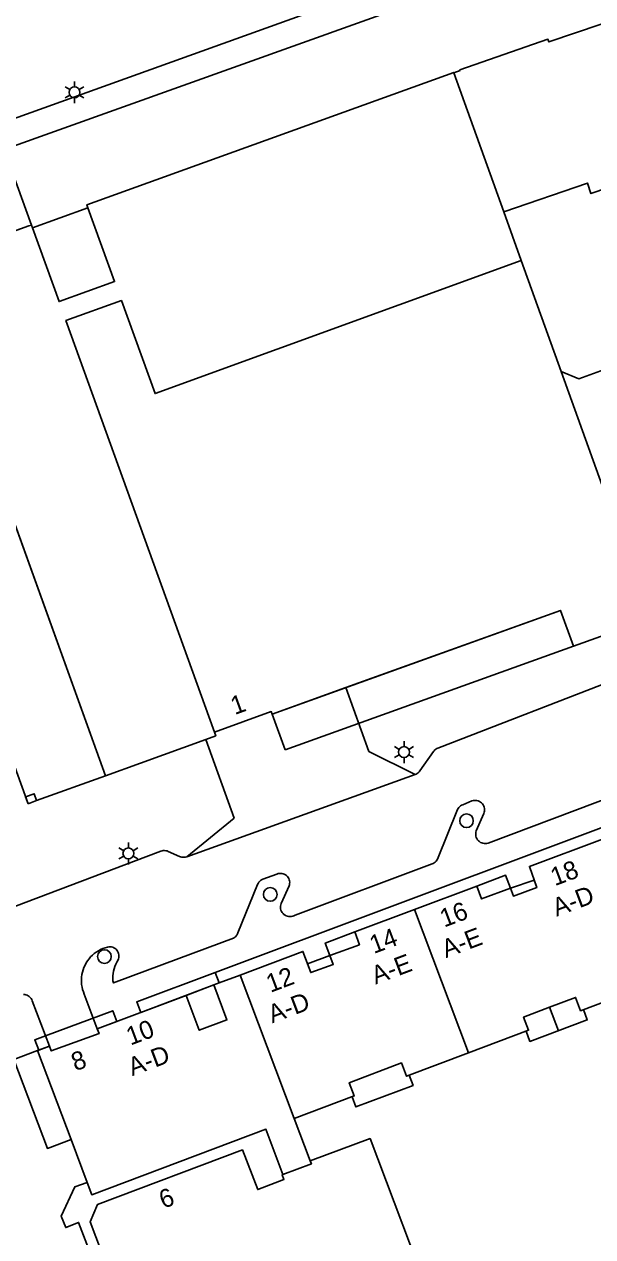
# Model space of a CAD drawing. Extents: x 122462 to 123306, y 485548 to 486417.
# Drawn here: x 122519.5 to 122566.2, y 485673.5 to 485773.2 of the extents above; entities that cross this region are included whole.
import ezdxf

# ---------------------------------------------------------------- set-up
doc = ezdxf.new("R2010")
doc.units = 0
for name, color, linetype in [('B-WE-IE-MEUBILAIR_WEGMEUBILAIR_VERKEERSBORD-S', 7, 'Continuous'), ('Level 1', 7, 'Continuous'), ('Level 10', 7, 'Continuous'), ('Level 11', 7, 'Continuous'), ('Level 17', 7, 'Continuous'), ('Level 19', 7, 'Continuous'), ('Level 22', 7, 'Continuous'), ('Level 34', 7, 'Continuous'), ('Level 4', 7, 'Continuous'), ('Level 50', 7, 'Continuous'), ('Level 53', 7, 'Continuous'), ('N-WE-AL-T25', 7, 'Continuous')]:
    doc.layers.add(name, color=color, linetype=linetype)

msp = doc.modelspace()

# ---------------------------------------------------------------- linework, layer by layer
at = {"layer": 'Level 1'}
for p, q in [((122524.761, 485758.082), (122520.199, 485756.429)), ((122560.372, 485753.746), (122558.935, 485757.75)), ((122563.647, 485744.62), (122560.372, 485753.746)), ((122570.939, 485724.289), (122563.647, 485744.62)), ((122532.832, 485693.313), (122535.1, 485694.168)), ((122525.531, 485690.561), (122532.832, 485693.313)), ((122518.673, 485688.045), (122520.616, 485688.777)), ((122520.616, 485688.777), (122521.591, 485689.151)), ((122541.714, 485683.189), (122543.026, 485679.702))]:
    msp.add_line(p, q, dxfattribs=at)
for points in [[(122595.705, 485783.261), (122588.35, 485780.749), (122588.42, 485780.539), (122577.601, 485776.821), (122577.531, 485777.031), (122573.371, 485775.601), (122573.443, 485775.393), (122562.65, 485771.719), (122562.57, 485771.939), (122555.33, 485769.42), (122555.347, 485769.372), (122554.835, 485769.176)], [(122558.935, 485757.75), (122565.807, 485760.105), (122566.103, 485759.241), (122573.182, 485761.667), (122572.886, 485762.531), (122575.552, 485763.445), (122576.058, 485761.968), (122583.208, 485764.419), (122582.702, 485765.895), (122585.619, 485766.895), (122585.915, 485766.032), (122592.763, 485768.378), (122592.467, 485769.242), (122599.667, 485771.71)], [(122554.835, 485769.176), (122554.82, 485769.209), (122524.67, 485758.329), (122524.761, 485758.082)], [(122520.199, 485756.429), (122520.11, 485756.65), (122519.901, 485756.601), (122516.856, 485755.503), (122511.049, 485753.41), (122518.197, 485733.594), (122526.209, 485711.38), (122529.079, 485712.419), (122534.438, 485714.36)], [(122545.965, 485718.624), (122563.597, 485724.974), (122564.658, 485722.028), (122570.939, 485724.289)], [(122535.163, 485714.962), (122539.822, 485716.649), (122539.898, 485716.439), (122545.965, 485718.624)], [(122534.438, 485714.36), (122535.269, 485714.66), (122535.163, 485714.962)], [(122551.589, 485700.372), (122556.719, 485702.299), (122557.108, 485701.246), (122559.488, 485702.127), (122559.73, 485701.474), (122561.644, 485702.183), (122561.039, 485703.92), (122567.04, 485706.164)], [(122537.268, 485694.984), (122542.429, 485696.929), (122543.077, 485695.183), (122544.916, 485695.863), (122544.651, 485696.58), (122547.068, 485697.473), (122546.689, 485698.529), (122551.589, 485700.372)], [(122535.1, 485694.168), (122535.555, 485694.339), (122537.268, 485694.984)], [(122571.262, 485694.96), (122570.331, 485694.609), (122570.543, 485694.046), (122565.253, 485692.054), (122564.842, 485693.145), (122562.701, 485692.339)], [(122562.701, 485692.339), (122560.561, 485691.533), (122560.972, 485690.442), (122556.033, 485688.582)], [(122521.591, 485689.151), (122521.739, 485688.743), (122525.672, 485690.172), (122525.531, 485690.561)], [(122556.033, 485688.582), (122550.942, 485686.664), (122550.531, 485687.755), (122546.233, 485686.137), (122546.644, 485685.045), (122541.714, 485683.189)], [(122543.026, 485679.702), (122547.951, 485681.541), (122553.241, 485667.511), (122546.311, 485664.908), (122547.777, 485661.013)]]:
    msp.add_lwpolyline(points, dxfattribs=at)
at = {"layer": 'Level 10'}
for points in [[(122519.84, 485709.069), (122520.535, 485709.334), (122526.209, 485711.38), (122511.049, 485753.41), (122519.901, 485756.601), (122520.11, 485756.65), (122514.9, 485771.059), (122514.741, 485770.971), (122514.241, 485770.791), (122514.141, 485771.021), (122508.443, 485768.964), (122508.528, 485768.729), (122507.89, 485768.498), (122507.805, 485768.733), (122506.416, 485768.232), (122506.501, 485767.997), (122505.862, 485767.766), (122505.777, 485768.001), (122500.08, 485765.961), (122500.159, 485765.742), (122499.489, 485765.499), (122519.84, 485709.069)], [(122540.959, 485713.492), (122539.898, 485716.439), (122563.597, 485724.974), (122564.658, 485722.028), (122540.959, 485713.492)], [(122559.488, 485702.127), (122561.43, 485702.801), (122561.644, 485702.183), (122559.73, 485701.474), (122559.488, 485702.127)], [(122544.651, 485696.58), (122544.916, 485695.863), (122543.077, 485695.183), (122542.812, 485695.9), (122544.651, 485696.58)], [(122529.103, 485691.907), (122528.772, 485692.784), (122535.229, 485695.204), (122535.555, 485694.339), (122529.103, 485691.907)], [(122521.739, 485688.743), (122521.591, 485689.151), (122520.717, 485688.815), (122520.395, 485689.646), (122521.279, 485689.977), (122526.796, 485692.045), (122527.128, 485691.163), (122525.531, 485690.561), (122525.672, 485690.172), (122521.739, 485688.743)]]:
    msp.add_lwpolyline(points, dxfattribs=at)
at = {"layer": 'Level 11'}
for points in [[(122556.719, 485702.299), (122559.09, 485703.189), (122559.488, 485702.127)], [(122546.689, 485698.529), (122544.261, 485697.618), (122544.651, 485696.58)], [(122565.484, 485692.141), (122565.801, 485691.301), (122561.085, 485689.525), (122560.768, 485690.365)], [(122551.172, 485686.751), (122551.489, 485685.911), (122546.783, 485684.139), (122546.467, 485684.978)]]:
    msp.add_lwpolyline(points, dxfattribs=at)
at = {"layer": 'Level 17'}
msp.add_line((122551.651, 485711.476), (122532.876, 485704.714), dxfattribs=at)
for points in [[(122553.788, 485778.048), (122513.731, 485763.641)], [(122556.723, 485776.778), (122517.869, 485762.854)], [(122551.651, 485711.476), (122547.856, 485713.372), (122545.965, 485718.624)], [(122568.671, 485719.499), (122553.517, 485713.644), (122553.431, 485713.605), (122553.351, 485713.556), (122553.277, 485713.498), (122553.21, 485713.432), (122553.152, 485713.358), (122552.034, 485711.768), (122551.973, 485711.692), (122551.903, 485711.624), (122551.825, 485711.564), (122551.741, 485711.515), (122551.651, 485711.476)], [(122534.438, 485714.36), (122536.767, 485707.89), (122532.876, 485704.714)], [(122541.486, 485699.803), (122541.593, 485699.827), (122541.694, 485699.866), (122541.79, 485699.919), (122553.053, 485704.118), (122553.144, 485704.162), (122553.228, 485704.216), (122553.306, 485704.28), (122553.375, 485704.354), (122553.434, 485704.435), (122553.483, 485704.523), (122555.143, 485708.605), (122555.187, 485708.694), (122555.244, 485708.775), (122555.312, 485708.847), (122555.39, 485708.908), (122555.476, 485708.957), (122555.568, 485708.993), (122556.321, 485709.299), (122556.422, 485709.328), (122556.526, 485709.342), (122556.632, 485709.343), (122556.736, 485709.329), (122556.837, 485709.3), (122556.934, 485709.259), (122557.024, 485709.204), (122557.106, 485709.138), (122557.178, 485709.061), (122557.238, 485708.975), (122557.287, 485708.881), (122557.322, 485708.782), (122557.343, 485708.679), (122557.35, 485708.574), (122557.343, 485708.469), (122557.321, 485708.366), (122557.286, 485708.267), (122556.68, 485706.842), (122556.649, 485706.737), (122556.633, 485706.629), (122556.633, 485706.52), (122556.648, 485706.412), (122556.678, 485706.307), (122556.722, 485706.207), (122556.78, 485706.114), (122556.85, 485706.031), (122556.932, 485705.958), (122557.022, 485705.897), (122557.121, 485705.85), (122557.225, 485705.817), (122557.333, 485705.799), (122557.442, 485705.796), (122557.55, 485705.808), (122557.656, 485705.836), (122568.344, 485709.854)], [(122532.876, 485704.714), (122532.777, 485704.685), (122532.676, 485704.669), (122532.573, 485704.666), (122532.47, 485704.677), (122532.37, 485704.701), (122532.274, 485704.737), (122531.363, 485705.15), (122531.265, 485705.187), (122531.164, 485705.211), (122531.06, 485705.221), (122530.956, 485705.218), (122530.853, 485705.201), (122530.753, 485705.171), (122530.52, 485705.083), (122508.8, 485696.87)], [(122525.531, 485690.561), (122524.456, 485693.415), (122524.382, 485693.606), (122524.321, 485693.802), (122524.275, 485694.002), (122524.244, 485694.204), (122524.227, 485694.409), (122524.225, 485694.614), (122524.238, 485694.818), (122524.266, 485695.021), (122524.308, 485695.222), (122524.364, 485695.419), (122524.435, 485695.612), (122524.519, 485695.798), (122524.617, 485695.979), (122524.727, 485696.151), (122524.85, 485696.316), (122524.984, 485696.471), (122525.129, 485696.616), (122525.284, 485696.75), (122525.449, 485696.872), (122525.621, 485696.983), (122525.802, 485697.08), (122525.988, 485697.165), (122526.181, 485697.235), (122526.378, 485697.292), (122526.483, 485697.31), (122526.589, 485697.313), (122526.695, 485697.302), (122526.798, 485697.275), (122526.896, 485697.234), (122526.988, 485697.179), (122527.07, 485697.112), (122527.143, 485697.034), (122527.203, 485696.947), (122527.251, 485696.852), (122527.285, 485696.751), (122527.304, 485696.646), (122527.308, 485696.54), (122527.297, 485696.434), (122527.271, 485696.331), (122527.231, 485696.232), (122527.134, 485696.057), (122527.049, 485695.877), (122526.976, 485695.691), (122526.915, 485695.501), (122526.866, 485695.307), (122526.83, 485695.11), (122526.807, 485694.912), (122526.797, 485694.713), (122526.799, 485694.513), (122526.865, 485694.338), (122532.236, 485696.349), (122536.722, 485698.029), (122536.806, 485698.075), (122536.883, 485698.133), (122536.95, 485698.201), (122537.008, 485698.278), (122537.054, 485698.362), (122537.087, 485698.452), (122538.706, 485702.432), (122538.749, 485702.524), (122538.805, 485702.61), (122538.872, 485702.688), (122538.948, 485702.755), (122539.033, 485702.812), (122539.125, 485702.857), (122540.289, 485703.289), (122540.388, 485703.323), (122540.49, 485703.343), (122540.595, 485703.349), (122540.699, 485703.34), (122540.801, 485703.317), (122540.899, 485703.28), (122540.991, 485703.23), (122541.075, 485703.168), (122541.15, 485703.095), (122541.214, 485703.012), (122541.265, 485702.922), (122541.304, 485702.825), (122541.329, 485702.723), (122541.34, 485702.619), (122541.337, 485702.515), (122541.319, 485702.412), (122541.287, 485702.312), (122540.639, 485700.859), (122540.606, 485700.755), (122540.589, 485700.647), (122540.586, 485700.538), (122540.599, 485700.43), (122540.627, 485700.324), (122540.669, 485700.224), (122540.724, 485700.13), (122540.793, 485700.045), (122540.872, 485699.97), (122540.961, 485699.907), (122541.058, 485699.857), (122541.161, 485699.821), (122541.268, 485699.8), (122541.377, 485699.794), (122541.486, 485699.803)], [(122521.591, 485689.151), (122520.182, 485692.879), (122520.139, 485692.974), (122520.084, 485693.063), (122520.017, 485693.144), (122519.941, 485693.215), (122519.856, 485693.276), (122519.764, 485693.326), (122519.667, 485693.363), (122519.565, 485693.387), (122519.461, 485693.398)]]:
    msp.add_lwpolyline(points, dxfattribs=at)
at = {"layer": 'Level 19'}
msp.add_lwpolyline([(122568.113, 485745.115), (122565.115, 485743.997), (122563.647, 485744.62)], dxfattribs=at)
at = {"layer": 'Level 22'}
msp.add_line((122562.701, 485692.339), (122563.43, 485690.408), dxfattribs=at)
msp.add_lwpolyline([(122535.229, 485695.204), (122577.981, 485711.222), (122578.295, 485710.39)], dxfattribs=at)
at = {"layer": 'Level 34'}
msp.add_lwpolyline([(122519.84, 485709.069), (122519.633, 485709.646), (122520.332, 485709.898), (122520.535, 485709.334), (122519.84, 485709.069)], dxfattribs=at)
at = {"layer": 'Level 4'}
for p, q in [((122558.935, 485757.75), (122554.835, 485769.176)), ((122556.033, 485688.582), (122551.589, 485700.372)), ((122520.616, 485688.777), (122523.372, 485681.458)), ((122523.372, 485681.458), (122524.704, 485677.919))]:
    msp.add_line(p, q, dxfattribs=at)
for points in [[(122543.026, 485679.702), (122543.121, 485679.451), (122540.79, 485678.573), (122539.383, 485682.311), (122525.079, 485676.924), (122524.704, 485677.919)], [(122524.809, 485672.502), (122523.991, 485674.651), (122522.931, 485674.221), (122522.571, 485675.171), (122523.671, 485677.571), (122524.704, 485677.919)]]:
    msp.add_lwpolyline(points, dxfattribs=at)
at = {"layer": 'Level 50'}
for p, q in [((122523.656, 485768.018), (122523.656, 485768.468)), ((122523.266, 485767.793), (122522.876, 485768.018)), ((122524.435, 485768.018), (122524.045, 485767.793)), ((122523.266, 485767.343), (122522.876, 485767.118)), ((122523.656, 485766.668), (122523.656, 485767.118)), ((122524.435, 485767.118), (122524.045, 485767.343)), ((122550.349, 485713.541), (122549.959, 485713.766)), ((122550.739, 485713.766), (122550.739, 485714.216)), ((122551.518, 485713.766), (122551.128, 485713.541)), ((122550.349, 485713.091), (122549.959, 485712.866)), ((122550.739, 485712.416), (122550.739, 485712.866)), ((122551.518, 485712.866), (122551.128, 485713.091)), ((122528.088, 485705.436), (122528.088, 485705.886)), ((122527.698, 485705.211), (122527.308, 485705.436)), ((122527.698, 485704.761), (122527.308, 485704.536)), ((122528.867, 485705.436), (122528.477, 485705.211)), ((122528.867, 485704.536), (122528.477, 485704.761)), ((122528.088, 485704.086), (122528.088, 485704.536))]:
    msp.add_line(p, q, dxfattribs=at)
for centre in [(122523.656, 485767.568), (122550.739, 485713.316), (122528.088, 485704.986)]:
    msp.add_circle(centre, 0.45, dxfattribs=at)
at = {"layer": 'Level 53'}
for centre in [(122555.875, 485707.67), (122539.74, 485701.615), (122526.114, 485696.508)]:
    msp.add_circle(centre, 0.56, dxfattribs=at)
at = {"layer": 'N-WE-AL-T25'}
for p, q in [((122537.268, 485694.985), (122537.268, 485694.984)), ((122537.268, 485694.984), (122541.714, 485683.189))]:
    msp.add_line(p, q, dxfattribs=at)
for points in [[(122520.199, 485756.429), (122522.389, 485750.362), (122526.953, 485752.009), (122524.761, 485758.082)], [(122560.372, 485753.746), (122530.278, 485742.793), (122527.517, 485750.444), (122522.954, 485748.798), (122535.163, 485714.962)], [(122532.832, 485693.313), (122533.914, 485690.444), (122536.182, 485691.299), (122535.1, 485694.168)], [(122518.673, 485688.045), (122521.429, 485680.726), (122523.372, 485681.458)], [(122540.79, 485678.573), (122540.72, 485678.547), (122540.861, 485678.171), (122538.711, 485677.351), (122537.451, 485680.611), (122525.551, 485676.121), (122524.931, 485674.691), (122531.891, 485656.271), (122533.261, 485655.591), (122547.777, 485661.013)]]:
    msp.add_lwpolyline(points, dxfattribs=at)

# ---------------------------------------------------------------- texts
at = {"layer": 'B-WE-IE-MEUBILAIR_WEGMEUBILAIR_VERKEERSBORD-S'}
for s, rotation, p in [('1', 19.93758, (122536.821, 485716.361)), ('18', 20.59886, (122563.132, 485702.29)), ('A-D', 20.59886, (122563.274, 485699.771)), ('16', 20.59886, (122554.037, 485698.888)), ('14', 20.59886, (122548.254, 485696.714)), ('A-E', 20.59886, (122554.179, 485696.368)), ('A-E', 20.59886, (122548.395, 485694.194)), ('12', 20.59886, (122539.759, 485693.521)), ('A-D', 20.59886, (122539.902, 485691.002)), ('10', 20.59886, (122528.256, 485689.182)), ('8', 19.9468, (122523.724, 485687.071)), ('A-D', 20.59886, (122528.399, 485686.663)), ('6', 20.69047, (122530.958, 485675.757))]:
    msp.add_text(s, height=1.5, rotation=rotation, dxfattribs=at).set_placement(p)

doc.saveas('drawing.dxf')
